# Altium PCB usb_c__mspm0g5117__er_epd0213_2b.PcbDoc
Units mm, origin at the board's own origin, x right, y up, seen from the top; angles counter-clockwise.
Board outline 64 x 33 mm, 2 copper layers (Top, Bottom), stack 0 mm thick; 41 components, 34 nets, 206 pads, 92 vias.
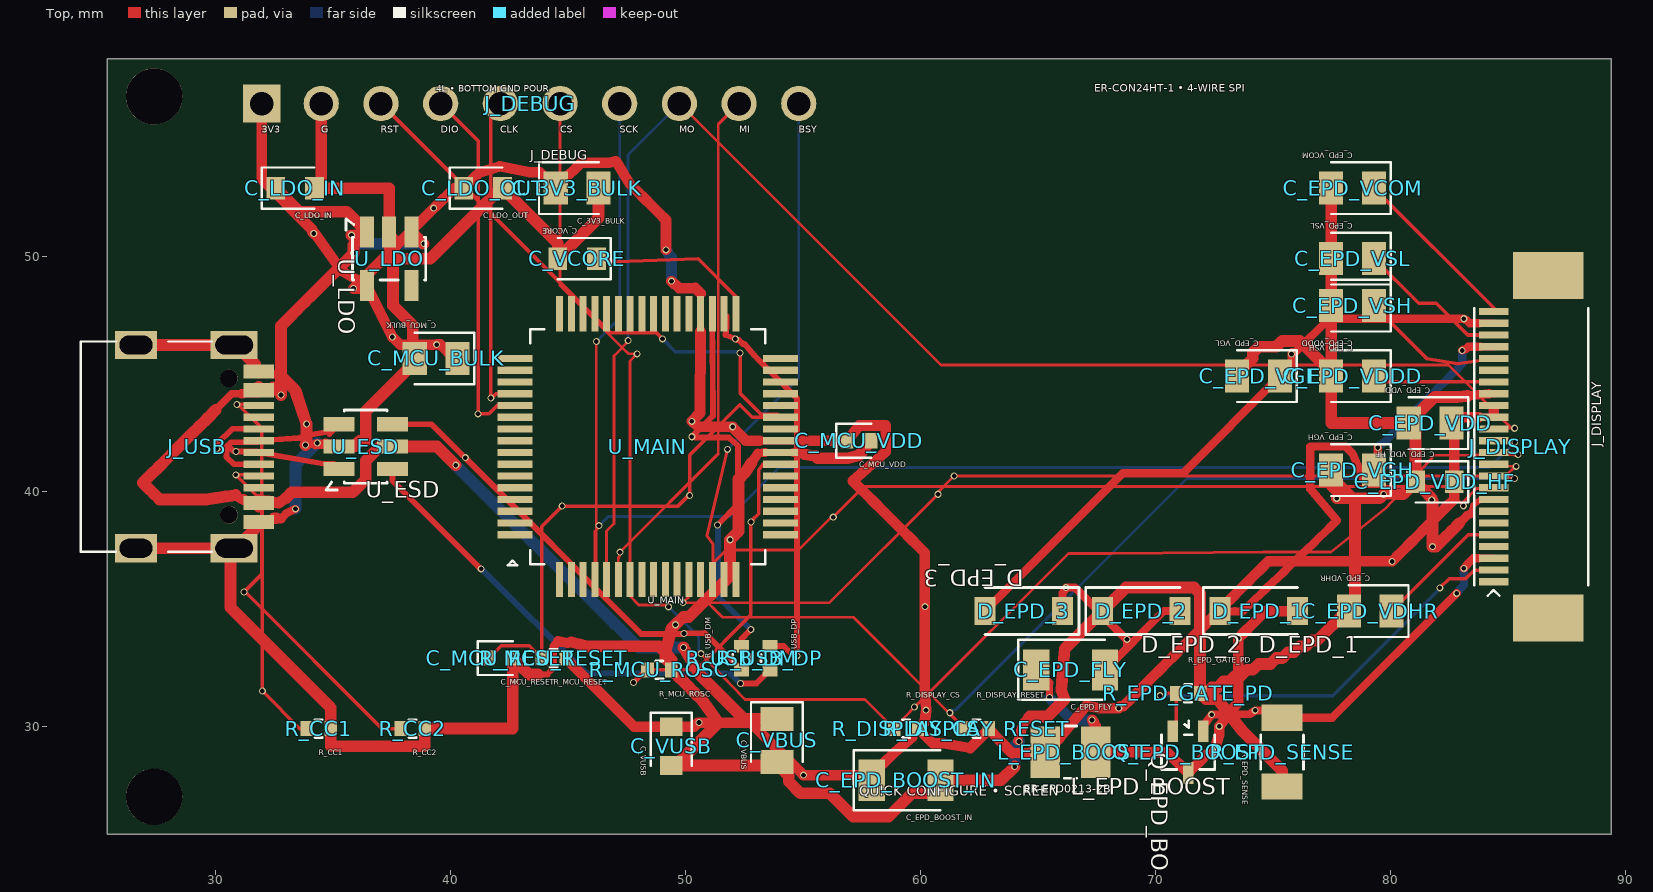
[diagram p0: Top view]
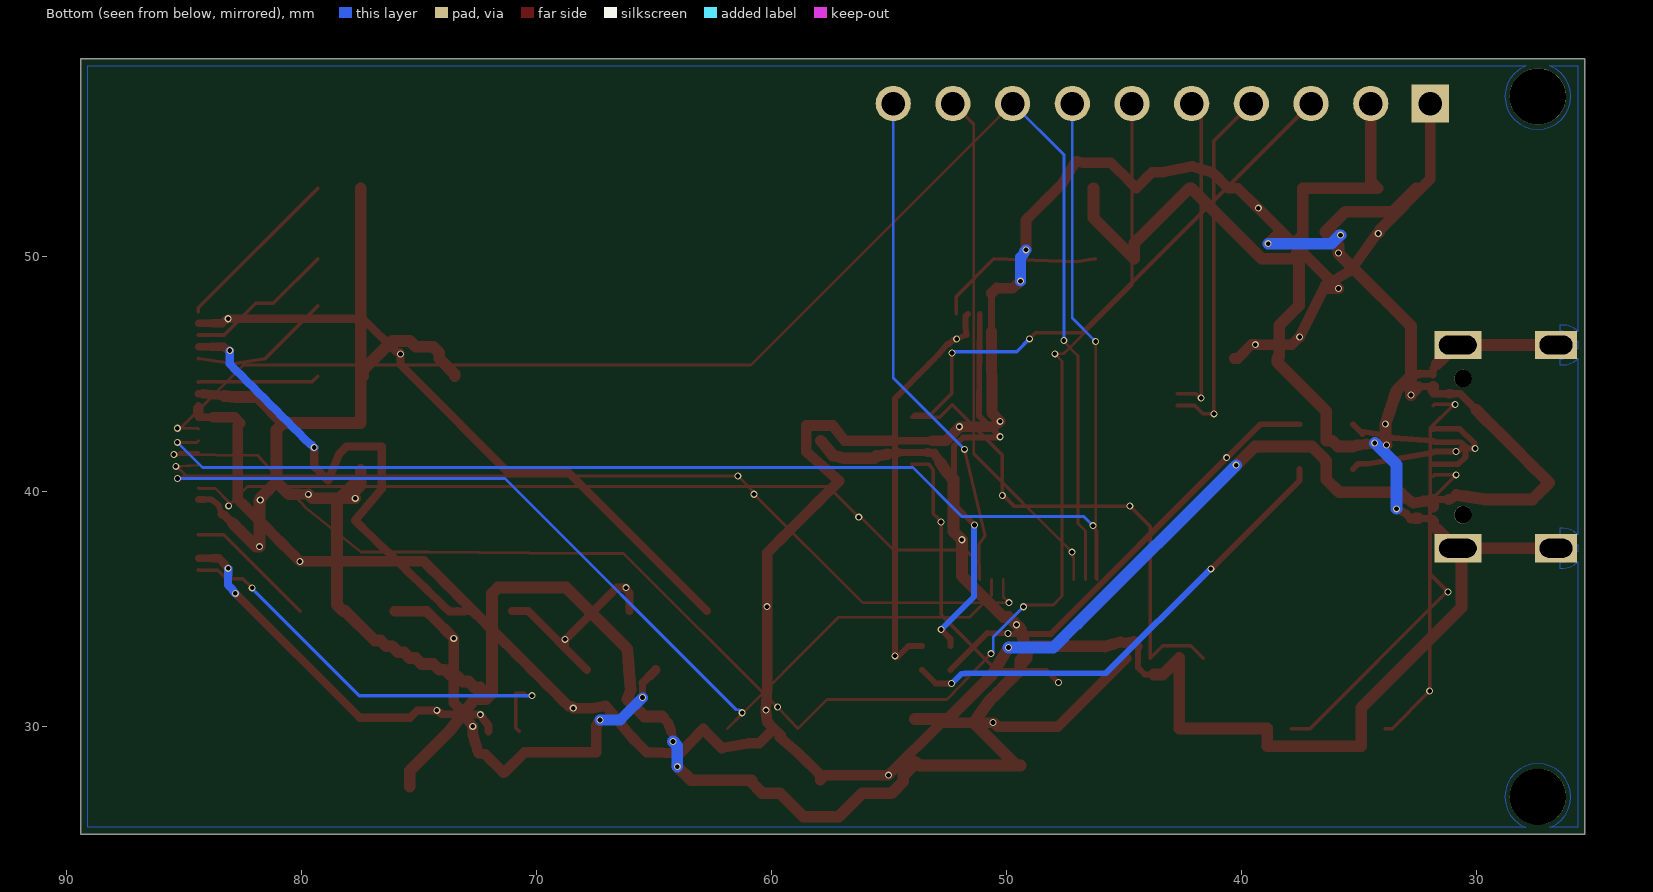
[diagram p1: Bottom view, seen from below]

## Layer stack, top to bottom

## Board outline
25.4,58.4 89.4,58.4 89.4,25.4 25.4,25.4

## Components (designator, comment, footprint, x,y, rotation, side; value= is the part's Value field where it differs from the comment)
C_3V3_BULK "" TSCIRCUIT-2.8500x1.4000mm 45.4,52.9 r0 top
C_EPD_BOOST_IN "" TSCIRCUIT-4.0500x1.7500mm 59.4,27.7 r0 top
C_EPD_FLY "" TSCIRCUIT-4.0500x1.7500mm 66.4,32.4 r0 top
C_EPD_VCOM "" TSCIRCUIT-2.8500x1.4000mm 78.4,52.9 r180 top
C_EPD_VDD "" TSCIRCUIT-2.8500x1.4000mm 81.7,42.9 r180 top
C_EPD_VDD_HF "" TSCIRCUIT-2.4500x0.9500mm 81.9,40.4 r180 top
C_EPD_VDDD "" TSCIRCUIT-2.8500x1.4000mm 78.4,44.9 r180 top
C_EPD_VDHR "" TSCIRCUIT-2.8500x1.4000mm 79.15,34.9 r180 top
C_EPD_VGH "" TSCIRCUIT-2.8500x1.4000mm 78.4,40.9 r180 top
C_EPD_VGL "" TSCIRCUIT-2.8500x1.4000mm 74.4,44.9 r180 top
C_EPD_VSH "" TSCIRCUIT-2.8500x1.4000mm 78.4,47.9 r180 top
C_EPD_VSL "" TSCIRCUIT-2.8500x1.4000mm 78.4,49.9 r180 top
C_LDO_IN "" TSCIRCUIT-2.4500x0.9500mm 33.4,52.9 r0 top
C_LDO_OUT "" TSCIRCUIT-2.4500x0.9500mm 41.4,52.9 r0 top
C_MCU_BULK "" TSCIRCUIT-2.8500x1.4000mm 39.4,45.65 r180 top
C_MCU_RESET "" TSCIRCUIT-1.5600x0.6400mm 42.15,32.9 r0 top
C_MCU_VDD "" TSCIRCUIT-1.5600x0.6400mm 57.4,42.15 r0 top
C_VBUS "" TSCIRCUIT-1.4000x2.8500mm 53.9,29.4 r270 top
C_VCORE "" TSCIRCUIT-2.4500x0.9500mm 45.4,49.9 r180 top
C_VUSB "" TSCIRCUIT-0.9500x2.4500mm 49.4,29.15 r270 top
D_EPD_1 "" TSCIRCUIT-4.2000x1.2000mm 74.4,34.9 r0 top
D_EPD_2 "" TSCIRCUIT-4.2000x1.2000mm 69.4,34.9 r0 top
D_EPD_3 "" TSCIRCUIT-4.2000x1.2000mm 64.4,34.9 r180 top
J_DEBUG "" TSCIRCUIT-24.3600x1.5000mm 43.4,56.5 r0 top
J_DISPLAY "" TSCIRCUIT-4.4500x16.5800mm 86,41.9 r90 top
J_USB "" TSCIRCUIT-6.7732x9.8502mm 29.112,41.9 r90 top
L_EPD_BOOST "" TSCIRCUIT-3.4000x2.2000mm 66.4,28.9 r0 top
Q_EPD_BOOST "" TSCIRCUIT-1.7500x2.7000mm 71.4,28.9 r270 top
R_CC1 "" TSCIRCUIT-1.5600x0.6400mm 34.4,29.9 r0 top
R_CC2 "" TSCIRCUIT-1.5600x0.6400mm 38.4,29.9 r0 top
R_DISPLAY_CS "" TSCIRCUIT-1.5600x0.6400mm 59.4,29.9 r0 top
R_DISPLAY_RESET "" TSCIRCUIT-1.5600x0.6400mm 62.4,29.9 r0 top
R_EPD_GATE_PD "" TSCIRCUIT-1.5600x0.6400mm 71.4,31.4 r0 top
R_EPD_SENSE "" TSCIRCUIT-1.7500x4.0500mm 75.4,28.9 r270 top
R_MCU_RESET "" TSCIRCUIT-1.5600x0.6400mm 44.4,32.9 r0 top
R_MCU_ROSC "" TSCIRCUIT-1.5600x0.6400mm 48.9,32.4 r0 top
R_USB_DM "" TSCIRCUIT-0.6400x1.5600mm 52.4,32.9 r90 top
R_USB_DP "" TSCIRCUIT-0.6400x1.5600mm 53.6,32.9 r90 top
U_ESD "" TSCIRCUIT-3.6000x2.5000mm 36.4,41.9 r0 top
U_LDO "" TSCIRCUIT-2.5000x3.6000mm 37.4,49.9 r270 top
U_MAIN "" TSCIRCUIT-12.8000x12.8000mm 48.4,41.9 r0 top

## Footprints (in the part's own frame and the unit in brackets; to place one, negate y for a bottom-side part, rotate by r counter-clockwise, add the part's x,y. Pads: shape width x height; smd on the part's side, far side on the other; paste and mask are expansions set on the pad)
TSCIRCUIT-0.6400x1.5600mm [mm]
  rect 0.54x0.64 smd: 1(-0.51,0) 2(0.51,0)
  silkscreen extent -0.15,-0.38 0.15,0.38
TSCIRCUIT-0.9500x2.4500mm [mm]
  rect 0.8x0.95 smd: 1(-0.825,0) 2(0.825,0)
  silkscreen extent -1.43,-0.87 0.82,0.87
TSCIRCUIT-1.4000x2.8500mm [mm]
  rect 1.025x1.4 smd: 1(-0.913,0) 2(0.913,0)
  silkscreen extent -1.63,-1.1 0.91,1.1
TSCIRCUIT-1.5600x0.6400mm [mm]
  rect 0.54x0.64 smd: 1(-0.51,0) 2(0.51,0)
  silkscreen extent -0.98,-0.72 0.51,0.72
TSCIRCUIT-1.7500x2.7000mm [mm]
  rect 0.925x0.45 smd: 1(-0.887,-0.65) 2(-0.887,0.65) 3(0.888,0)
  silkscreen extent -1.32,-1.13 0.73,1.14
TSCIRCUIT-1.7500x4.0500mm [mm]
  rect 1.125x1.75 smd: 1(-1.462,0) 2(1.463,0)
  silkscreen extent -0.73,-0.91 0.73,0.91
TSCIRCUIT-2.4500x0.9500mm [mm]
  rect 0.8x0.95 smd: 1(-0.825,0) 2(0.825,0)
  silkscreen extent -1.43,-0.87 0.82,0.87
TSCIRCUIT-2.5000x3.6000mm [mm]
  rect 1.325x0.6 smd: 1(-1.138,-0.95) 2(-1.138,0) 3(-1.138,0.95) 4(1.137,0.95) 5(1.137,-0.95)
  silkscreen extent -1.69,-1.84 0.91,1.56
TSCIRCUIT-2.8500x1.4000mm [mm]
  rect 1.025x1.4 smd: 1(-0.913,0) 2(0.913,0)
  silkscreen extent -1.63,-1.1 0.91,1.1
TSCIRCUIT-3.4000x2.2000mm [mm]
  rect 1.25x2.2 smd: 1(-1.075,0) 2(1.075,0)
  silkscreen extent -0.26,-1.11 0.26,1.11
TSCIRCUIT-3.6000x2.5000mm [mm]
  rect 1.325x0.6 smd: 1(-1.138,-0.95) 2(-1.138,0) 3(-1.138,0.95) 4(1.137,0.95) 5(1.137,0) 6(1.137,-0.95)
  silkscreen extent -1.69,-1.84 0.91,1.56
TSCIRCUIT-4.0500x1.7500mm [mm]
  rect 1.125x1.75 smd: 1(-1.463,0) 2(1.462,0)
  silkscreen extent -2.22,-1.28 1.46,1.27
TSCIRCUIT-4.2000x1.2000mm [mm]
  rect 0.9x1.2 smd: 1(-1.65,0) 2(1.65,0)
  silkscreen extent -2.36,-1 1.65,1
TSCIRCUIT-4.4500x16.5800mm [mm]
  rect 0.3x1.25 smd: 1(-5.75,1.6) 2(-5.25,1.6) 3(-4.75,1.6) 4(-4.25,1.6) 5(-3.75,1.6) 6(-3.25,1.6) 7(-2.75,1.6) 8(-2.25,1.6) 9(-1.75,1.6) 10(-1.25,1.6) 11(-0.75,1.6) 12(-0.25,1.6) 13(0.25,1.6) 14(0.75,1.6) 15(1.25,1.6) 16(1.75,1.6) 17(2.25,1.6) 18(2.75,1.6) 19(3.25,1.6) 20(3.75,1.6) 21(4.25,1.6) 22(4.75,1.6) 23(5.25,1.6) 24(5.75,1.6)
  rect 2x3 smd: 25(7.29,-0.725) 26(-7.29,-0.725)
  silkscreen extent -6.35,-2.42 5.9,2.43
TSCIRCUIT-6.7732x9.8502mm [mm]
  rect 0.3x1.3 smd: 1(-3.35,-2.737) 2(-3.05,-2.737) 3(-2.55,-2.737) 4(-2.25,-2.737) 5(-1.75,-2.737) 6(-1.25,-2.737) 7(-0.75,-2.737) 8(-0.25,-2.737) 9(0.25,-2.737) 10(0.75,-2.737) 11(1.25,-2.737) 12(1.75,-2.737) 13(2.55,-2.737) 14(2.25,-2.737) 15(3.35,-2.737) 16(3.05,-2.737)
  rect 1.2x2 hole 0.8 slot 1.6 at 90 deg: 17(-4.325,-1.693) 18(4.325,-1.693)
  rect 1.2x1.8 hole 0.8 slot 1.4 at 90 deg: 19(4.325,2.487) 20(-4.325,2.487)
  round 0.75 hole 0.75 unplated: NPTH-1(-2.9,-1.468) NPTH-2(2.9,-1.468)
  silkscreen extent -4.47,-0.75 4.47,4.83
TSCIRCUIT-12.8000x12.8000mm [mm]
  rect 1.5x0.3 smd: 1(-5.65,-3.75) 2(-5.65,-3.25) 3(-5.65,-2.75) 4(-5.65,-2.25) 5(-5.65,-1.75) 6(-5.65,-1.25) 7(-5.65,-0.75) 8(-5.65,-0.25) 9(-5.65,0.25) 10(-5.65,0.75) 11(-5.65,1.25) 12(-5.65,1.75) 13(-5.65,2.25) 14(-5.65,2.75) 15(-5.65,3.25) 16(-5.65,3.75) 33(5.65,3.75) 34(5.65,3.25) 35(5.65,2.75) 36(5.65,2.25) 37(5.65,1.75) 38(5.65,1.25) 39(5.65,0.75) 40(5.65,0.25) 41(5.65,-0.25) 42(5.65,-0.75) 43(5.65,-1.25) 44(5.65,-1.75) 45(5.65,-2.25) 46(5.65,-2.75) 47(5.65,-3.25) 48(5.65,-3.75)
  rect 0.3x1.5 smd: 17(-3.75,5.65) 18(-3.25,5.65) 19(-2.75,5.65) 20(-2.25,5.65) 21(-1.75,5.65) 22(-1.25,5.65) 23(-0.75,5.65) 24(-0.25,5.65) 25(0.25,5.65) 26(0.75,5.65) 27(1.25,5.65) 28(1.75,5.65) 29(2.25,5.65) 30(2.75,5.65) 31(3.25,5.65) 32(3.75,5.65) 49(3.75,-5.65) 50(3.25,-5.65) 51(2.75,-5.65) 52(2.25,-5.65) 53(1.75,-5.65) 54(1.25,-5.65) 55(0.75,-5.65) 56(0.25,-5.65) 57(-0.25,-5.65) 58(-0.75,-5.65) 59(-1.25,-5.65) 60(-1.75,-5.65) 61(-2.25,-5.65) 62(-2.75,-5.65) 63(-3.25,-5.65) 64(-3.75,-5.65)
  silkscreen extent -5.95,-5.05 5,5
TSCIRCUIT-24.3600x1.5000mm [mm]
  rect 1.6x1.6 hole 1: 1(-11.43,0)
  round 1.5 hole 1: 2(-8.89,0) 3(-6.35,0) 4(-3.81,0) 5(-1.27,0) 6(1.27,0) 7(3.81,0) 8(6.35,0) 9(8.89,0) 10(11.43,0)

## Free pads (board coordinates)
  round 2.4 hole 2.4 unplated: NPTH-3(27.4,27) NPTH-4(27.4,56.8)

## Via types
v1: diameter 0.3, hole 0.2, Top to Bottom, 92 vias

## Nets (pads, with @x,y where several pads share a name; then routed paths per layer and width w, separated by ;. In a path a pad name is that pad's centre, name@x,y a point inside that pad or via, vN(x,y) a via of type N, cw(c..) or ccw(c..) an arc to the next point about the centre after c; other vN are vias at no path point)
".J_DEBUG > .pin4 to .U_MAIN > .pin12": J_DEBUG.4 U_MAIN.12 | length 15.6
  Top w0.15: J_DEBUG.4 41.184,54.906 v1(41.184,43.295) 41.186,43.297 41.647,43.297 42,43.65 U_MAIN.12
".J_DEBUG > .pin5 to .U_MAIN > .pin13": J_DEBUG.5 U_MAIN.13 | length 13.8
  Top w0.15: J_DEBUG.5 41.728,56.098 v1(41.728,43.969) 41.772,44.013 41.807,44.013 41.943,44.15 U_MAIN.13
".J_DISPLAY > .pin5 to .C_EPD_VDHR > .pin1": C_EPD_VDHR.1 J_DISPLAY.5 | length 5.7
  Top w0.15: C_EPD_VDHR.1 83.313,38.15 J_DISPLAY.5
".J_DISPLAY > .pin18 to .C_EPD_VDDD > .pin1": C_EPD_VDDD.1 J_DISPLAY.18 | length 5.2
  Top w0.15: C_EPD_VDDD.1 79.563,44.655 J_DISPLAY.18
".J_DISPLAY > .pin20 to .C_EPD_VSH > .pin1": C_EPD_VSH.1 J_DISPLAY.20 | length 6.1
  Top w0.15: C_EPD_VSH.1 81.563,45.645 82.879,45.424 J_DISPLAY.20
".J_DISPLAY > .pin22 to .C_EPD_VSL > .pin1": C_EPD_VSL.1 J_DISPLAY.22 | length 6.4
  Top w0.15: C_EPD_VSL.1 81.218,47.995 81.957,47.995 83.303,46.65 J_DISPLAY.22
".J_DISPLAY > .pin24 to .C_EPD_VCOM > .pin1": C_EPD_VCOM.1 J_DISPLAY.24 | length 7.4
  Top w0.15: C_EPD_VCOM.1 84.4,47.813 J_DISPLAY.24
".U_MAIN > .pin42 to .R_MCU_ROSC > .pin1": R_MCU_ROSC.1 U_MAIN.42 | length 14.4
  Top w0.15: R_MCU_ROSC.1 47.89,31.9 v1(47.8,31.864) 47.906,32.006 48.306,32.406 50.466,32.404 52.794,34.735 v1(52.794,38.689) 52.896,38.791 52.896,38.819 53.123,39.046 53.125,40.888 53.3,41.15 U_MAIN.42
DISPLAY_BUSY_N: J_DEBUG.10 J_DISPLAY.9 U_MAIN.51 | length 57.7
  Top w0.12: v1(51.796,41.783) 50.92,38.12 51.183,37.735 51.183,36.283 U_MAIN.51 51.15,36.906 51.747,37.503 54.827,37.503 56.183,38.859 56.257,38.859 v1(56.298,38.9) 57.597,40.199 82.257,40.199 82.308,40.199 82.978,39.529 82.978,39.515 v1(83.113,39.38) 83.113,39.557 83.671,40.114 84.364,40.114 J_DISPLAY.9
  Bottom w0.12: v1(51.796,41.783) 51.954,41.941 54.83,44.817 J_DEBUG.10
DISPLAY_CS_N: J_DEBUG.6 J_DISPLAY.12 R_DISPLAY_CS.1 U_MAIN.58 | length 69.1
  Top w0.12: J_DEBUG.6 44.67,48.767 47.334,46.104 47.586,45.851 v1(47.953,45.851) 47.65,45.548 U_MAIN.58 47.65,35.538 48.023,35.164 49.165,35.164 49.241,35.088 49.287,35.088 v1(49.29,35.085) ; v1(50.667,33.087) 52.545,31.137 57.653,31.137 R_DISPLAY_CS.1 v1(59.751,30.822) 59.832,30.841 59.832,30.876 66.31,37.354 68.166,37.354 74.61,37.422 77.475,37.418 79.815,39.29 81.877,41.518 v1(85.446,41.567) 85.433,41.514 85.344,41.514 85.208,41.65 J_DISPLAY.12
  Bottom w0.12: v1(49.29,35.085) 50.574,33.801 50.574,33.119 50.574,33.108 v1(50.667,33.087)
DISPLAY_DC: J_DISPLAY.11 U_MAIN.53 | length 40
  Top w0.12: U_MAIN.53 50.15,35.505 49.971,35.325 v1(49.907,35.258) 56.142,35.261 60.747,39.866 v1(60.754,39.873) 60.754,39.96 61.398,40.604 61.398,40.606 v1(61.443,40.651) 84.91,40.651 85.362,41.103 v1(85.359,41.06) 84.441,41.109 J_DISPLAY.11
DISPLAY_MISO: J_DEBUG.9 U_MAIN.59 | length 22.4
  Top w0.12: U_MAIN.59 47.15,37.168 47.208,37.226 47.208,37.397 v1(47.22,37.409) 51.407,41.596 51.407,55.617 J_DEBUG.9
DISPLAY_MOSI: J_DEBUG.8 J_DISPLAY.14 U_MAIN.60 | length 63.8
  Top w0.12: U_MAIN.60 46.65,38.309 46.962,38.621 46.962,45.764 47.567,46.369 47.567,46.42 v1(47.57,46.416) ; J_DEBUG.8 60.883,45.367 75.638,45.367 82.481,45.367 85.23,42.617 v1(85.294,42.681) 84.431,42.681 J_DISPLAY.14
  Bottom w0.12: v1(47.57,46.416) 47.57,54.32 J_DEBUG.8
DISPLAY_RESET_N: J_DISPLAY.10 R_DISPLAY_RESET.1 U_MAIN.52 | length 44.3
  Top w0.12: U_MAIN.52 50.65,35.567 51.581,34.636 57.154,34.636 R_DISPLAY_RESET.1 61.258,30.532 v1(61.258,30.574) ; J_DISPLAY.10 85.039,40.65 85.117,40.571 85.263,40.571 v1(85.287,40.547)
  Bottom w0.12: v1(61.258,30.574) 61.3,30.616 61.388,30.704 61.513,30.704 71.356,40.547 v1(85.287,40.547)
DISPLAY_SCLK: J_DEBUG.7 J_DISPLAY.13 U_MAIN.61 | length 64.4
  Top w0.12: v1(46.215,46.371) 46.215,36.315 U_MAIN.61 46.15,38.28 46.278,38.408 46.278,38.482 v1(46.33,38.534) ; J_DISPLAY.13 84.469,42.081 v1(85.294,42.081)
  Bottom w0.12: v1(46.215,46.371) 46.243,46.399 46.243,46.401 47.21,47.368 J_DEBUG.7 ; v1(46.33,38.534) 46.723,38.927 51.915,38.927 53.996,41.008 57.072,41.008 84.217,41.008 85.244,42.035 85.248,42.035 v1(85.294,42.081)
EPD_GDR: J_DISPLAY.2 Q_EPD_BOOST.1 R_EPD_GATE_PD.1 | length 18.8
  Top w0.15: v1(70.2,31.3) 70.432,31.3 70.532,31.4 R_EPD_GATE_PD.1 70.89,29.927 Q_EPD_BOOST.1 ; v1(82.114,35.891) 82.506,36.283 83.204,36.279 83.575,36.642 J_DISPLAY.2
  Bottom w0.15: v1(70.2,31.3) 77.56,31.3 82.071,35.811 82.071,35.848 v1(82.114,35.891)
EPD_PUMP: C_EPD_FLY.2 D_EPD_2.2 D_EPD_3.1 | length 10.5
  Top w0.35: D_EPD_3.1 66.05,35.676 66.208,35.834 66.208,35.892 v1(66.2,35.9) 66.587,35.9 68.787,33.7 v1(68.8,33.7) 68.8,33.337 C_EPD_FLY.2 70.363,34.9 D_EPD_2.2
EPD_RESE: J_DISPLAY.3 Q_EPD_BOOST.2 R_EPD_SENSE.1 | length 16.3
  Top w0.3: J_DISPLAY.3@83.775,37.15 83.838,37.15 83.931,37.15 84.025,37.15 84.119,37.15 84.213,37.15 84.306,37.15 J_DISPLAY.3
  Top w0.35: Q_EPD_BOOST.2 72.05,30.009 v1(72.403,30.494) 74.046,30.517 74.137,30.608 74.185,30.608 v1(74.253,30.676) 75.086,30.676 R_EPD_SENSE.1 77.531,30.362 v1(82.828,35.659) ; v1(83.131,36.718) 83.256,36.843 83.262,36.89 83.522,37.15 83.65,37.15 83.744,37.15 J_DISPLAY.3@83.775,37.15
  Bottom w0.35: v1(82.828,35.659) 82.923,35.754 82.923,35.802 83.137,36.016 v1(83.131,36.718)
EPD_SWITCH: C_EPD_FLY.1 D_EPD_1.2 L_EPD_BOOST.2 Q_EPD_BOOST.3 | length 19
  Top w0.288: v1(65.497,31.222) C_EPD_FLY.1@65.497,31.531
  Top w0.3: C_EPD_FLY.1@65.497,31.531 C_EPD_FLY.1@65.497,31.841
  Top w0.35: C_EPD_FLY.1@65.217,32.12 C_EPD_FLY.1@65.497,31.841
  Top w0.4: C_EPD_FLY.1 C_EPD_FLY.1@65.217,32.12
  Top w0.45: v1(67.313,30.266) 67.386,30.193 67.386,30.113 67.475,30.025 67.475,29.65 67.475,29.275 L_EPD_BOOST.2 70.513,28.9 Q_EPD_BOOST.3 71.665,28.277 71.93,28.543 72.195,28.807 72.475,28.85 72.725,29.666 v1(72.725,29.994) 72.742,30.011 73.269,30.729 73.533,30.992 73.533,31.385 73.533,31.778 73.533,32.171 73.533,32.564 73.533,32.956 73.533,33.349 v1(73.533,33.742) 73.532,33.741 73.821,34.031 74.111,34.321 74.4,34.61 74.69,34.9 75.03,34.9 75.37,34.9 75.71,34.9 D_EPD_1.2
  Bottom w0.45: v1(65.497,31.222) 65.736,30.983 65.975,30.744 66.214,30.505 66.453,30.266 66.883,30.266 v1(67.313,30.266)
EPD_VGH: C_EPD_VGH.1 D_EPD_1.1 J_DISPLAY.21 | length 21.9
  Top w0.3: J_DISPLAY.21@83.855,46.15 84.128,46.15 J_DISPLAY.21
  Top w0.35: D_EPD_1.1 73.071,34.895 73.391,34.889 73.712,34.884 73.963,35.126 74.215,35.368 74.467,35.609 74.718,35.851 74.97,36.093 75.221,36.335 75.473,36.576 75.725,36.818 75.976,37.06 76.228,37.302 76.48,37.544 76.731,37.785 76.983,38.027 77.234,38.269 77.486,38.511 77.738,38.752 76.6,40.1 76.6,41.9 78.1,41.9 78.4,41.6 78.877,40.464 79.095,40.682 C_EPD_VGH.1 79.472,41.059 79.472,41.328 79.472,41.596 v1(79.472,41.865) ; v1(83.061,45.987) 83.121,46.036 83.197,46.036 83.311,46.15 83.583,46.15 J_DISPLAY.21@83.855,46.15
  Bottom w0.35: v1(79.472,41.865) 79.596,41.989 79.635,41.989 79.88,42.234 80.125,42.478 80.369,42.723 80.614,42.968 80.859,43.213 81.103,43.457 81.348,43.702 81.593,43.947 81.838,44.191 82.082,44.436 82.327,44.681 82.572,44.925 82.816,45.17 83.061,45.415 83.061,45.701 v1(83.061,45.987)
EPD_VGL: C_EPD_VGL.1 D_EPD_3.2 J_DISPLAY.23 | length 27.2
  Top w0.3: J_DISPLAY.23@83.775,47.15 83.838,47.15 83.931,47.15 84.025,47.15 84.119,47.15 84.213,47.15 84.306,47.15 J_DISPLAY.23
  Top w0.35: D_EPD_3.2 68.615,40.765 71.178,40.765 C_EPD_VGL.1 75.8,45.387 v1(75.8,45.842) 75.824,45.924 75.97,45.924 77.388,47.341 v1(83.132,47.341) 83.164,47.309 83.216,47.309 83.375,47.15 83.65,47.15 83.744,47.15 J_DISPLAY.23@83.775,47.15
GND: C_3V3_BULK.2 C_EPD_BOOST_IN.2 C_EPD_VCOM.2 C_EPD_VDD.2 C_EPD_VDD_HF.2 C_EPD_VDDD.2 C_EPD_VDHR.2 C_EPD_VGH.2 C_EPD_VGL.2 C_EPD_VSH.2 C_EPD_VSL.2 C_LDO_IN.2 C_LDO_OUT.2 C_MCU_BULK.2 C_MCU_RESET.2 C_MCU_VDD.2 C_VBUS.2 C_VCORE.2 C_VUSB.2 D_EPD_2.1 J_DEBUG.2 J_DISPLAY.8 J_DISPLAY.17 J_USB.1 J_USB.2 J_USB.15 J_USB.16 J_USB.17 J_USB.18 J_USB.19 J_USB.20 R_CC1.2 R_CC2.2 R_EPD_GATE_PD.2 R_EPD_SENSE.2 R_MCU_ROSC.2 U_ESD.2 U_LDO.2 U_MAIN.41 | length 202.8
  Top w0.25: 44.12,32.203 44.408,32.491 44.408,32.922 44.408,33.353 ; 83.4,39.025 83.525,39.4 83.842,39.65 J_DISPLAY.8@84.121,39.65
  Top w0.275: J_USB.1@31.849,38.7 J_USB.2 ; J_USB.16 J_USB.16@31.899,45 ; 43.738,32.203 44.12,32.203
  Top w0.288: J_USB.16 J_USB.16@31.849,45.1
  Top w0.3: J_USB.1@31.699,38.4 J_USB.1 J_USB.1@31.849,38.7 ; 31.699,45.4 J_USB.15 J_USB.16@31.849,45.1 ; J_USB.2 31.945,38.839 32.037,38.85 32.13,38.85 32.224,38.85 32.318,38.85 32.412,38.85 32.499,38.85 ; J_USB.16@31.899,45 J_USB.16@32.4,45 ; U_MAIN.41@53.399,41.65 53.725,41.65 U_MAIN.41 54.144,41.65 54.237,41.65 54.331,41.65 54.425,41.65 54.519,41.65 U_MAIN.41@54.612,41.65 ; J_DISPLAY.8@84.121,39.65 J_DISPLAY.8
  Top w0.312: v1(33.835,41.97) v1@34.267,41.991
  Top w0.325: v1(34.343,42.056) U_ESD.2@34.736,42.044 ; 44.408,33.353 44.408,33.395 ; v1@64.13,29.37 v1(64.2,29.355) ; J_DISPLAY.17@84.215,44.143 J_DISPLAY.17
  Top w0.35: 32.807,38.85 32.999,39.042 v1(33.411,39.251) ; U_ESD.2@34.736,42.044 35.13,42.033 U_ESD.2 ; v1@64.13,29.37 64.28,29.776
  Top w0.375: J_USB.16@32.4,45 32.8,44.9 ; 44.408,33.395 44.588,33.619 ; 53.088,41.619 U_MAIN.41@53.399,41.65 ; 82.938,38.635 83.268,38.965 83.4,39.025
  Top w0.4: 52.819,41.21 53.088,41.619 ; U_MAIN.41@54.612,41.65 55.077,41.573 ; 83.301,44.058 83.758,44.1 J_DISPLAY.17@84.215,44.143
  Top w0.425: 32.599,38.85 32.807,38.85 ; v1@34.267,41.991 U_ESD.2@34.698,42.012 ; 64.28,29.776 64.431,30.181 64.619,30.369
  Top w0.437: 44.588,33.619 44.997,33.543 45.15,33.587
  Top w0.45: U_ESD.2@34.698,42.012 34.98,41.956 U_ESD.2 ; v1(79.722,39.872) 80.135,39.872
  Top w0.475: 45.15,33.587 45.483,33.49
  Top w0.5: J_USB.20 J_USB.17 ; J_USB.19 J_USB.18 ; J_USB.18 30.874,46.225 31.474,45.625 31.699,45.4 ; J_USB.1@31.699,38.4 31.474,38.175 30.874,37.575 J_USB.17 30.65,37.419 30.65,35.9 30.65,35.051 30.805,34.897 34.91,30.791 R_CC1.2 34.91,29.15 38.91,29.15 R_CC2.2 42.66,29.9 C_MCU_RESET.2 43.008,32.551 43.357,32.203 43.738,32.203 ; 32.499,38.85 32.505,38.85 32.599,38.85 ; 32.8,44.9 33.4,44.3 v1(33.887,42.866) 33.887,42.022 v1(33.835,41.97) ; J_DEBUG.2 34.51,53.185 C_LDO_IN.2 37.4,52.9 U_LDO.2 ; U_ESD.2 35.9,41.9 36.15,42.15 36.4,42.15 36.4,43.4 38.487,45.488 C_MCU_BULK.2 38.483,45.65 38.4,45.733 38.4,47.067 37.567,47.9 37.567,50.733 37.4,50.9 U_LDO.2 ; 45.483,33.49 45.816,33.393 45.824,33.4 48.9,33.4 49.15,33.15 ; C_3V3_BULK.2 46.313,51.637 C_VCORE.2 44.575,50.55 C_LDO_OUT.2 42.15,52.9 39.15,49.9 37.65,49.9 37.65,50.15 37.4,50.4 U_LDO.2 ; 52.819,41.21 52.551,40.802 52.269,40.519 52.269,40.075 52.269,39.63 52.269,39.185 52.269,38.74 52.269,38.296 52.074,38.101 v1(51.909,37.936) 51.909,36.409 50.15,34.65 49.915,34.65 v1(49.584,34.319) 49.41,34.145 49.41,34.1 49.15,33.15 ; 55.077,41.573 55.541,41.496 55.633,41.405 56.93,41.405 57.4,41.525 C_MCU_VDD.2 ; v1(64.017,28.283) 63.434,27.7 C_EPD_BOOST_IN.2 60.9,27.662 60.9,27.65 60.4,27.15 59.65,27.15 58.65,26.15 57.15,26.15 56.15,27.15 54.9,27.15 54.4,27.65 54.4,27.9 53.9,28.4 C_VBUS.2 53.737,28.325 C_VUSB.2 49.575,28.325 51.4,30.15 50.715,31.114 50.389,31.435 50.063,31.757 49.736,32.078 R_MCU_ROSC.2 ; 64.619,30.369 64.664,30.414 64.875,30.414 65.414,30.414 66.15,31.15 66,31.53 66.037,31.972 66.074,32.414 66.111,32.856 66.149,33.299 66.469,33.619 66.789,33.939 67.109,34.259 67.43,34.58 D_EPD_2.1 68.75,35.9 71.65,35.9 71.9,35.65 71.91,35.42 71.91,34.973 71.91,34.527 71.91,34.08 71.91,33.633 71.91,33.187 71.91,32.74 71.91,32.293 71.91,31.847 R_EPD_GATE_PD.2 ; C_EPD_VGL.2 73.488,44.987 74.15,45.65 74.15,45.9 74.4,46.15 75.15,46.15 75.4,46.4 76.15,46.4 77.4,45.15 77.4,44.9 C_EPD_VDDD.2 ; R_EPD_SENSE.2 75.4,28.106 73.705,29.8 72.65,31.15 72.16,31.15 R_EPD_GATE_PD.2 ; C_EPD_VSH.2 C_EPD_VDDD.2 ; C_EPD_VSH.2 C_EPD_VSL.2@77.488,49.899 ; C_EPD_VSL.2 C_EPD_VCOM.2 ; v1(79.722,39.872) 79.707,39.857 79.548,39.698 79.167,39.698 78.787,39.698 78.406,39.698 v1(77.725,39.7) 78.037,39.709 77.762,39.984 77.488,40.259 77.488,40.579 C_EPD_VGH.2 77.488,40.602 78.506,39.584 78.506,35.168 C_EPD_VDHR.2 78.15,34.9 76.9,33.65 76.65,33.65 76.4,33.4 76.15,33.4 75.9,33.15 75.65,33.15 75.4,32.9 75.15,32.9 74.9,32.65 74.4,32.65 74.15,32.4 73.9,32.4 73.65,32.15 73.4,32.15 73.15,31.9 72.9,31.9 72.65,31.65 72.4,31.65 72.15,31.4 R_EPD_GATE_PD.2 ; 80.135,39.872 80.547,39.872 80.811,40.136 C_EPD_VDD_HF.2 ; 82.938,38.635 82.608,38.305 82.279,37.975 81.949,37.645 v1(81.798,37.645) 81.798,39.598 v1(81.768,39.628) 81.768,39.707 81.422,40.053 C_EPD_VDD_HF.2 ; 83.301,44.058 82.845,44.016 81.903,44.016 C_EPD_VDD.2 ; 49.15,33.15 49.15,32.9 49.41,32.64 R_MCU_ROSC.2 ; 49.15,33.15 49.41,32.825 R_MCU_ROSC.2 ; C_EPD_VDDD.2 77.488,42.9 C_EPD_VDD.2 ; C_EPD_VDD.2 81.075,42.613 C_EPD_VDD_HF.2
  Bottom w0.5: v1(33.411,39.251) 33.411,41.124 v1(34.343,42.056) ; v1(64.017,28.283) 64.017,29.172 v1(64.2,29.355)
MAIN_RESET: C_MCU_RESET.1 J_DEBUG.3 R_MCU_RESET.1 U_MAIN.38 | length 45.4
  Top w0.15: J_DEBUG.3 46.798,46.756 48.762,46.755 v1(49.029,46.485) ; C_MCU_RESET.1 42.17,33.43 43.36,33.43 R_MCU_RESET.1 43.89,38.5 44.699,39.309 v1(44.761,39.371) 49.688,39.371 50.092,39.775 50.144,39.775 v1(50.185,39.816) 50.185,41.541 52.32,43.677 52.847,43.15 U_MAIN.38 53.933,43.267 53.239,43.267 52.342,44.163 v1(52.332,45.883)
  Bottom w0.15: v1(49.029,46.485) 49.579,45.935 52.299,45.935 v1(52.332,45.883)
MSP_VCORE: C_VCORE.1 U_MAIN.32 | length 7.3
  Top w0.15: C_VCORE.1 46.237,49.888 47.05,49.775 50.552,49.888 52.15,48.29 U_MAIN.32
usb-dm-mcu: R_USB_DM.2 U_MAIN.30 | length 17.4
  Top w0.25: U_MAIN.30 51.175,43.206 v1(50.278,42.321) 50.299,42.316 50.414,42.291 51.864,42.281 52.251,41.929 52.251,39.448 v1(51.368,38.565) ; R_USB_DM.2 52.4,33.725 52.707,34.033 52.707,34.038 v1(52.79,34.12)
  Bottom w0.25: v1(51.368,38.565) 51.393,38.54 51.393,35.517 v1(52.79,34.12)
usb-dm-phy: R_USB_DM.1 U_ESD.4 | length 19.2
  Top w0.25: U_ESD.4 39.199,42.85 40.499,41.55 ; 40.5,41.55 v1(40.641,41.429) 48.115,33.934 49.82,33.928 49.9,33.935 v1(49.949,33.948) 50.824,33.966 R_USB_DM.1
usb-dm-port: J_USB.7 J_USB.9 U_ESD.3 | length 7.1
  Top w0.25: J_USB.7 30.793,41.15 30.482,41.45 30.496,41.921 30.667,42.087 31.798,42.099 J_USB.9 33.566,42.266 33.73,42.35 34.81,42.53 34.857,42.444 U_ESD.3
usb-dp-mcu: R_USB_DP.2 U_MAIN.31 | length 17.5
  Top w0.25: U_MAIN.31 51.748,47.452 51.748,47.221 51.748,46.991 51.713,46.65 v1(52.131,46.483) 52.184,46.43 52.283,46.439 52.448,46.273 52.525,46.275 52.944,45.774 53.109,45.608 53.274,45.442 53.439,45.276 53.604,45.11 53.769,44.944 53.934,44.777 54.1,44.611 54.265,44.445 54.43,44.279 54.595,44.113 54.76,43.946 54.76,43.698 54.76,43.449 54.76,43.2 54.76,42.951 54.76,42.702 54.76,42.453 54.76,42.204 54.76,41.956 54.76,41.707 54.76,41.458 54.76,41.209 54.76,40.96 54.76,40.711 54.76,40.462 54.76,40.214 54.76,39.965 54.76,39.716 54.76,39.467 54.76,39.218 54.76,38.969 54.76,38.72 54.76,38.472 54.76,38.223 54.76,37.974 54.76,37.725 54.759,37.476 54.759,37.227 54.759,36.978 54.759,36.729 54.759,36.481 54.759,36.232 54.759,35.983 54.759,35.734 54.759,35.485 54.759,35.236 54.759,34.987 54.759,34.739 54.759,34.49 54.759,34.241 54.759,33.992 54.759,33.743 54.759,33.494 54.759,33.245 v1(54.759,32.997) 54.685,32.923 54.685,32.915 54.52,33.08 54.355,33.245 54.19,33.41 53.993,33.41 53.797,33.41 R_USB_DP.2
usb-dp-phy: R_USB_DP.1 U_ESD.6 | length 20.4
  Top w0.25: U_ESD.6 37.537,40.452 41.251,36.738 41.277,36.738 v1(41.317,36.698) ; v1(52.352,31.817) 53.027,31.817 R_USB_DP.1
  Bottom w0.25: v1(41.317,36.698) 45.781,32.258 51.767,32.246 51.929,32.234 52.343,31.82 52.349,31.82 v1(52.352,31.817)
usb-dp-port: J_USB.8 J_USB.10 U_ESD.1 | length 7.6
  Top w0.25: J_USB.10 30.731,42.659 30.093,42.038 30.11,41.865 v1(30.064,41.819) 30.664,41.819 30.769,41.714 30.837,41.714 v1(30.879,41.695) 31.804,41.695 J_USB.8 34.604,41.17 35.043,41.17 U_ESD.1
USB_CC1: J_USB.6 R_CC1.1 | length 13.2
  Top w0.15: J_USB.6 31.8,40.699 v1(30.877,40.699) 30.874,40.696 32,39.57 v1(32,31.5) 32.038,31.462 33.6,29.9 R_CC1.1
USB_CC2: J_USB.12 R_CC2.1 | length 18.8
  Top w0.15: J_USB.12 31.803,43.696 v1(30.916,43.696) 30.952,43.66 31.006,43.66 31.986,42.68 31.986,42.645 31.986,36.477 v1(31.225,35.713) 31.235,35.7 31.293,35.7 37.093,29.9 R_CC2.1
VBUS5: C_LDO_IN.1 C_VBUS.1 J_USB.3 J_USB.4 J_USB.13 J_USB.14 U_ESD.5 U_LDO.1 U_LDO.3 | length 59.7
  Top w0.3: 31.193,44.15 31.199,44.15 31.287,44.15 31.38,44.15 31.474,44.15 31.568,44.15 31.662,44.15 31.755,44.15 J_USB.14 J_USB.14@31.849,44.3 ; J_USB.4@31.199,39.65 31.287,39.65 31.38,39.65 31.474,39.65 31.568,39.65 31.661,39.65 31.755,39.65 J_USB.4 J_USB.3@31.849,39.5 ; J_USB.13 31.943,44.45 32.037,44.45 32.13,44.45 32.224,44.45 32.318,44.45 32.412,44.45 J_USB.13@32.45,44.45
  Top w0.325: 30.018,43.461 30.362,43.806 30.706,44.15 31.099,44.15
  Top w0.4: 30.869,39.837 31.099,39.65 31.193,39.65 31.199,39.65 ; 31.099,44.15 31.193,44.15
  Top w0.425: J_USB.13@32.45,44.45 32.485,44.415 32.489,44.411 32.555,44.345 32.727,44.173 v1(32.8,44.1)
  Top w0.475: J_USB.4 32.265,39.572 32.681,39.494 33.009,39.713
  Top w0.5: 30.018,43.461 29.673,43.117 29.329,42.772 28.985,42.428 28.64,42.084 28.296,41.739 27.951,41.395 27.607,41.051 27.263,40.706 26.918,40.362 27.156,40.125 27.393,39.887 27.63,39.65 28.126,39.65 28.621,39.65 29.117,39.65 29.612,39.65 30.031,39.713 30.45,39.775 30.869,39.837 ; J_USB.3 J_USB.3@31.849,39.5 ; J_USB.13@31.849,44.3 J_USB.13 ; C_LDO_IN.1 33.575,51.9 33.65,51.9 35.588,51.9 U_LDO.1 ; v1(32.8,44.1) 32.8,44.59 32.8,45.079 32.8,45.569 32.8,46.058 32.8,46.548 32.8,47.038 33.139,47.376 33.477,47.715 33.816,48.054 34.155,48.392 34.493,48.731 34.832,49.07 35.171,49.408 35.51,49.747 35.848,50.086 35.848,50.113 v1(35.878,50.143) 35.878,50.465 U_LDO.1 ; 33.009,39.713 33.252,39.955 35.505,39.955 35.855,39.955 36.4,40.5 36.4,41.3 37,41.9 U_ESD.5 39.448,41.9 v1(40.236,41.112) ; v1(35.8,50.9) 36.313,50.9 U_LDO.1 ; U_LDO.3 38.85,50.538 v1(38.875,50.538) ; v1(49.921,33.349) 50.65,32.15 52.487,30.312 C_VBUS.1
  Bottom w0.5: v1(35.8,50.9) 35.808,50.892 35.836,50.892 36.191,50.538 v1(38.875,50.538) ; v1(40.236,41.112) 46.993,34.354 47.011,34.354 48.016,33.349 v1(49.921,33.349)
VCC_3V3: C_3V3_BULK.1 C_EPD_BOOST_IN.1 C_EPD_VDD.1 C_EPD_VDD_HF.1 C_LDO_OUT.1 C_MCU_BULK.1 C_MCU_VDD.1 C_VUSB.1 J_DEBUG.1 J_DISPLAY.15 J_DISPLAY.16 L_EPD_BOOST.1 R_DISPLAY_CS.2 R_DISPLAY_RESET.2 R_MCU_RESET.2 U_LDO.5 U_MAIN.29 U_MAIN.40 | length 119.4
  Top w0.3: U_MAIN.29@50.65,46.8 50.65,46.875 50.65,46.988 50.65,47.1 50.65,47.212 50.65,47.325 50.65,47.437 U_MAIN.29 50.65,47.895 50.65,48.425 ; 53.3,42.15 53.375,42.15 53.488,42.15 53.6,42.15 53.713,42.15 53.825,42.15 53.937,42.15 U_MAIN.40 54.163,42.15 54.275,42.15 54.388,42.15 54.5,42.15 54.612,42.15 54.725,42.15 U_MAIN.40@54.8,42.15 ; J_DISPLAY.15@83.775,43.15 83.838,43.15 83.95,43.15 84.062,43.15 84.175,43.15 84.287,43.15 J_DISPLAY.15 84.4,43.3 ; J_DISPLAY.16@84.4,43.5 J_DISPLAY.16
  Top w0.337: 53.262,42.15 53.3,42.15
  Top w0.375: 53.15,42.15 53.262,42.15
  Top w0.437: 54.8,42.15 54.838,42.15
  Top w0.45: J_DEBUG.1 31.97,53.288 34.118,51.14 34.118,51.04 v1(34.191,50.967) 34.245,50.967 35.364,49.392 U_LDO.5 ; C_MCU_BULK.1 40.177,45.65 39.566,46.261 39.448,46.261 v1(39.423,46.237) 37.864,46.237 37.554,46.547 v1(37.537,46.564) U_LDO.5 ; R_MCU_RESET.2 47.835,29.975 C_VUSB.1 50.373,29.98 50.542,30.146 50.579,30.15 v1(50.582,30.156) 52.787,30.157 54.971,27.973 v1(55.033,27.919) 57.723,27.915 C_EPD_BOOST_IN.1 57.937,27.928 58.219,28.209 58.501,28.491 58.783,28.773 59.65,29.525 59.628,29.618 R_DISPLAY_CS.2 ; v1(49.18,50.276) 49.18,50.698 49.18,51.12 49.18,51.542 48.875,51.847 48.57,52.152 48.265,52.457 47.96,52.762 47.655,53.067 47.05,54.05 46.74,53.982 46.35,53.982 45.96,53.982 45.57,53.982 45.299,53.711 45.029,53.441 44.758,53.17 C_3V3_BULK.1 44.261,53.126 44.035,53.352 43.809,53.578 43.386,53.578 42.1,53.825 41.269,53.578 41.253,53.578 41.027,53.352 40.801,53.126 C_LDO_OUT.1 40.162,52.9 39.393,52.131 39.377,52.131 v1(39.295,52.049) 39.295,52.039 35.968,48.712 v1(35.882,48.626) 36.314,48.626 U_LDO.5 ; v1(49.414,48.939) 49.543,48.81 49.576,48.81 49.751,48.636 50.002,48.636 50.254,48.636 50.425,48.65 50.65,48.425 ; 50.65,46.8 50.65,46.762 50.65,46.65 50.626,43.331 v1(50.279,42.975) 50.335,42.918 50.353,42.918 50.563,42.755 v1(52.018,42.745) 52.03,42.704 52.584,42.15 53.15,42.15 ; 54.838,42.15 54.95,42.15 C_MCU_VDD.1 57.4,42.8 58.525,42.8 58.525,41.675 57.131,40.437 57.438,40.131 57.744,39.826 58.051,39.52 58.358,39.214 58.665,38.909 58.972,38.603 59.279,38.298 59.586,37.992 59.893,37.686 60.2,37.381 60.2,36.968 60.2,36.556 60.2,36.143 60.2,35.73 60.2,35.318 v1(60.2,35.088) 60.2,34.657 60.2,34.225 60.2,33.794 60.2,33.363 60.2,32.931 60.2,32.5 60.2,32.069 60.2,31.637 v1(60.248,30.687) 60.224,30.438 60.2,30.19 R_DISPLAY_CS.2 ; J_DISPLAY.15@83.775,43.15 83.725,43.15 83.612,43.15 83.5,43.15 82.863,43.15 C_EPD_VDD.1 82.725,42.788 C_EPD_VDD_HF.1 82.725,40.033 82.725,39.665 82.414,39.355 82.104,39.044 81.793,38.733 81.482,38.422 81.171,38.112 80.861,37.801 80.55,37.49 80.239,37.18 80.239,37.172 v1(80.082,37.015) 79.643,37.015 79.203,37.015 78.764,37.015 78.324,37.015 77.885,37.015 77.445,37.015 77.006,37.015 76.567,37.015 76.127,37.015 75.688,37.015 75.248,37.015 74.809,37.015 74.5,36.706 74.192,36.398 73.883,36.089 73.575,35.781 73.266,35.472 72.958,35.164 72.649,34.855 72.341,34.547 72.032,34.238 71.724,33.93 71.415,33.621 71.107,33.313 70.798,33.004 70.49,32.696 70.181,32.387 69.873,32.079 69.564,31.77 69.256,31.462 68.947,31.153 68.639,30.845 68.523,30.845 v1(68.448,30.77) 68.03,30.77 67.613,30.77 67.075,30.875 65.948,29.523 65.637,29.212 L_EPD_BOOST.1 63.91,28.856 R_DISPLAY_RESET.2 62.8,29.75 62.125,29.075 60.969,29.282 60.528,29.282 60.219,29.591 R_DISPLAY_CS.2 ; 84.4,43.3 J_DISPLAY.16@84.4,43.5
  Bottom w0.45: v1(49.18,50.276) 49.251,50.205 49.251,50.12 49.414,49.957 49.414,49.618 49.414,49.278 v1(49.414,48.939)
pads on no net: J_DISPLAY.1 J_DISPLAY.4 J_DISPLAY.6 J_DISPLAY.7 J_DISPLAY.19 J_DISPLAY.25 J_DISPLAY.26 J_USB.5 J_USB.11 J_USB.NPTH-1 J_USB.NPTH-2 U_LDO.4 U_MAIN.1 U_MAIN.2 U_MAIN.3 U_MAIN.4 U_MAIN.5 U_MAIN.6 U_MAIN.7 U_MAIN.8 U_MAIN.9 U_MAIN.10 U_MAIN.11 U_MAIN.14 U_MAIN.15 U_MAIN.16 U_MAIN.17 U_MAIN.18 U_MAIN.19 U_MAIN.20 U_MAIN.21 U_MAIN.22 U_MAIN.23 U_MAIN.24 U_MAIN.25 U_MAIN.26 U_MAIN.27 U_MAIN.28 U_MAIN.33 U_MAIN.34 U_MAIN.35 U_MAIN.36 U_MAIN.37 U_MAIN.39 U_MAIN.43 U_MAIN.44 U_MAIN.45 U_MAIN.46 U_MAIN.47 U_MAIN.48 U_MAIN.49 U_MAIN.50 U_MAIN.54 U_MAIN.55 U_MAIN.56 U_MAIN.57 U_MAIN.62 U_MAIN.63 U_MAIN.64

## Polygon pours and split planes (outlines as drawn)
GND on Bottom (solid): 26.886,58.1 25.7,58.1 25.7,46.796 25.725,46.826 25.854,46.932 26.001,47.01 26.16,47.059 26.326,47.075 26.476,47.075 26.476,46.825 26.326,46.825 26.209,46.814 26.096,46.779 25.993,46.724 25.902,46.649 25.827,46.558 25.772,46.455 25.747,46.375 25.7,46.375 25.7,46.075 25.747,46.075 25.772,45.996 25.827,45.892 25.902,45.801 25.993,45.726 26.096,45.671 26.209,45.637 26.326,45.625 26.476,45.625 26.476,45.375 26.326,45.375 26.16,45.391 26.001,45.44 25.854,45.518 25.725,45.624 25.7,45.654 25.7,38.146 25.725,38.176 25.854,38.282 26.001,38.36 26.16,38.409 26.326,38.425 26.476,38.425 26.476,38.175 26.326,38.175 26.209,38.163 26.096,38.129 25.993,38.074 25.902,37.999 25.827,37.908 25.772,37.804 25.747,37.725 25.7,37.725 25.7,37.425 25.747,37.425 25.772,37.345 25.827,37.242 25.902,37.151 25.993,37.076 26.096,37.021 26.209,36.986 26.326,36.975 26.476,36.975 26.476,36.725 26.326,36.725 26.16,36.741 26.001,36.79 25.854,36.868 25.725,36.974 25.7,37.004 25.7,25.7 26.886,25.7 26.864,25.707 26.622,25.836 26.41,26.01 26.236,26.222 26.107,26.464 26.027,26.727 26,27 26.027,27.273 26.107,27.536 26.236,27.778 26.41,27.99 26.622,28.164 26.864,28.293 27.127,28.373 27.4,28.4 27.673,28.373 27.936,28.293 28.178,28.164 28.39,27.99 28.564,27.778 28.693,27.536 28.773,27.273 28.8,27 28.773,26.727 28.693,26.464 28.564,26.222 28.39,26.01 28.178,25.836 27.936,25.707 27.914,25.7 89.1,25.7 89.1,58.1 27.914,58.1 27.936,58.093 28.178,57.964 28.39,57.79 28.564,57.578 28.693,57.336 28.773,57.073 28.8,56.8 28.773,56.527 28.693,56.264 28.564,56.022 28.39,55.81 28.178,55.636 27.936,55.507 27.673,55.427 27.4,55.4 27.127,55.427 26.864,55.507 26.622,55.636 26.41,55.81 26.236,56.022 26.107,56.264 26.027,56.527 26,56.8 26.027,57.073 26.107,57.336 26.236,57.578 26.41,57.79 26.622,57.964 26.864,58.093

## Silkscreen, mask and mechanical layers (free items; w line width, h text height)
Top Overlay:
  text "4L • BOTTOM GND POUR" at 39.4,56.9 h0.48
  text "ER-CON24HT-1 • 4-WIRE SPI" at 67.4,56.9 h0.55
  text "ER-EPD0213-2B" at 64.4,27.05 h0.58
  text "QUICK CONFIGURE • SCREEN" at 57.4,26.9 h0.72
